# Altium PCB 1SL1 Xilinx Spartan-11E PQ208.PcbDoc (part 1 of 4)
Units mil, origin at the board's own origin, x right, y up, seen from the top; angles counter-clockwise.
Board outline 7086.61 x 1988.19 mil, 2 copper layers (Top Layer, Bottom Layer), stack 29.698 mil thick; 115 components, 126 nets, 642 pads, 225 vias.
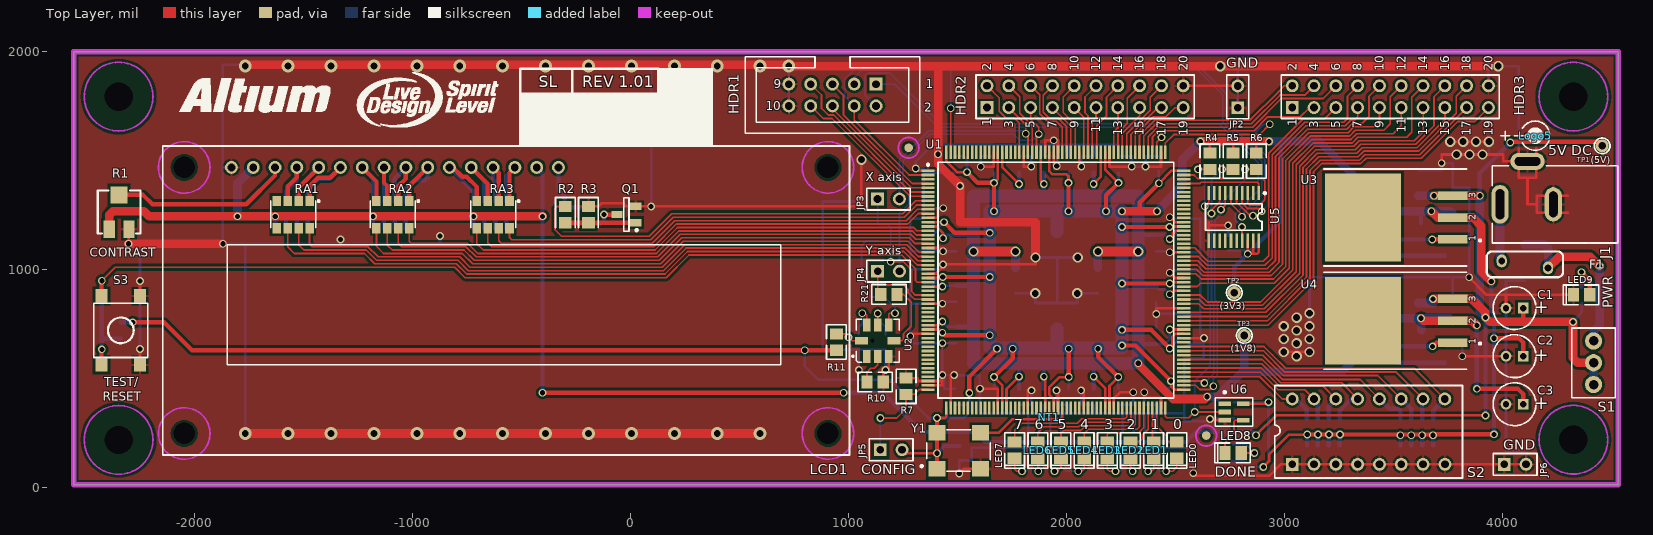
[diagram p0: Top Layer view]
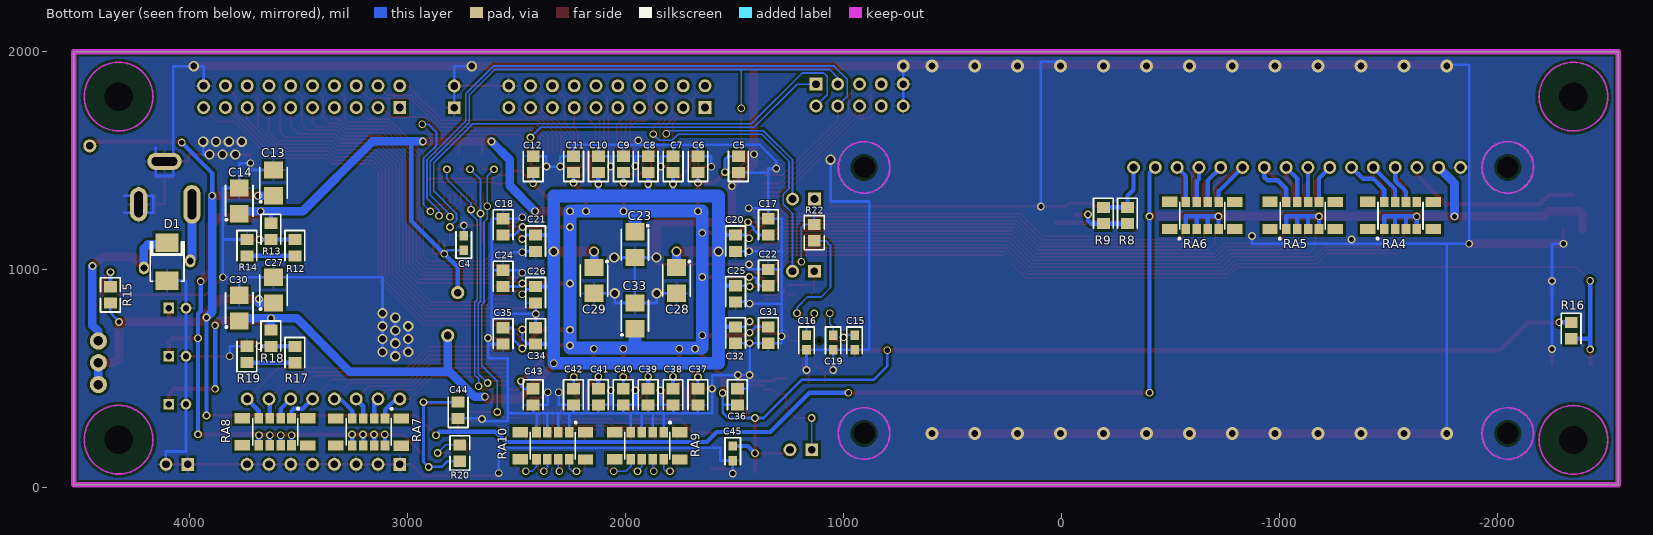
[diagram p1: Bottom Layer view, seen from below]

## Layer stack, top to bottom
Top Solder: solder mask 0.4, Solder Resist, Dk 3.5
Top Layer: signal copper 1.4
Dielectric 1: core 26.898, FR-4, Dk 4.2
Bottom Layer: signal copper 1.4
Bottom Solder: solder mask 0.4, Solder Resist, Dk 3.5

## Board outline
-2555.06,9.87 4531.55,9.87 4531.55,1998.06 -2555.06,1998.06

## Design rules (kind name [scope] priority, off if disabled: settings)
Clearance "Clearance_Power Polygon" [inpolygon and innetclass('Power')] p1: gap=11.81 ignorepadtopadclearanceinfootprint=FALSE except(0: Arc-Hole Track-Hole SMDPad-Hole THPad-Hole Via-Hole Fill-Hole Poly-Hole Region-Hole Text-Hole)
Clearance [All] p2: gap=7.87 ignorepadtopadclearanceinfootprint=FALSE except(0: Arc-Hole Track-Hole SMDPad-Hole THPad-Hole Via-Hole Fill-Hole Poly-Hole Region-Hole Text-Hole) // General
ComponentClearance ComponentClearance_D1_F1 [InComponent('D1') vs InComponent('F1')] p1 off: gap=1.18 collisioncheckmode=3 verticalgap=10 showdistances=FALSE
ComponentClearance ComponentClearance_JP4_R21 [InComponent('JP4') vs InComponent('R21')] p2 off: gap=2.76 collisioncheckmode=3 verticalgap=10 showdistances=FALSE
ComponentClearance ComponentClearance_LCD1_U2 [InComponent('LCD1') vs InComponent('U2')] p3 off: gap=3.54 collisioncheckmode=3 verticalgap=10 showdistances=FALSE
ComponentClearance ComponentClearance_U1_U6 [InComponent('U1') vs InComponent('U6')] p4 off: gap=3.94 collisioncheckmode=3 verticalgap=10 showdistances=FALSE
ComponentClearance ComponentClearance_S2 [InComponent('S2') vs InComponent('RA7') Or InComponent('RA8')] p5 off: gap=3.94 collisioncheckmode=3 verticalgap=10 showdistances=FALSE // Why is such a small clearance necessary?
ComponentClearance ComponentClearance_LCD1_R11 [InComponent('LCD1') vs InComponent('R11')] p6 off: gap=6.3 collisioncheckmode=3 verticalgap=10 showdistances=FALSE
ComponentClearance ComponentClearance_J1_Logo5 [InComponent('J1') vs InComponent('Logo5')] p7 off: gap=7.48 collisioncheckmode=3 verticalgap=10 showdistances=FALSE
ComponentClearance ComponentClearance_R2_R3 [InComponent('R2') vs InComponent('R3')] p8 off: gap=7.48 collisioncheckmode=3 verticalgap=10 showdistances=FALSE
ComponentClearance ComponentClearance_R5 [InComponent('R5') vs InComponent('R4') Or InComponent('R6')] p9 off: gap=7.48 collisioncheckmode=3 verticalgap=10 showdistances=FALSE
ComponentClearance ComponentClearance_LEDs [HasFootprint('SMD _LED') vs HasFootprint('SMD _LED')] p10 off: gap=7.48 collisioncheckmode=3 verticalgap=10 showdistances=FALSE
ComponentClearance ComponentClearance_R7_R10 [InComponent('R7') vs InComponent('R10')] p11 off: gap=9.45 collisioncheckmode=3 verticalgap=10 showdistances=FALSE
ComponentClearance ComponentClearance_U1 [InComponent('U1') vs Not InComponent('NT1') && Not InComponent('LED8')] p12 off: gap=10 collisioncheckmode=3 verticalgap=10 showdistances=FALSE
ComponentClearance ComponentClearance_General [Not InComponent('U1') vs Not InComponent('U1')] p13 off: gap=10 collisioncheckmode=3 verticalgap=10 showdistances=FALSE
ComponentClearance ComponentClearance_Default [All] p14: gap=5 collisioncheckmode=3 verticalgap=10 showdistances=FALSE
FabricationTestPointUsage TestPointUsage [All] p1 off: valid=0 allowmultiple=FALSE
FabricationTestpoint Testpoint [All] p1 off: side=3 testpointundercomponent=TRUE minsize=40 maxsize=100 preferedsize=60 minholesize=0 maxholesize=40 preferedholesize=32 testpointgrid=1 allowsidetop=TRUE allowsidebottom=TRUE usegrid=TRUE gridtolerance=0.01
HoleSize [All] p1: absolutevalues=TRUE maxlimit=130 minlimit=0 maxpercent=80.000 minpercent=20.000
PlaneConnect [All] p1: planeconnectstyle=Relief reliefexpansion=11.81 reliefentries=4 reliefconductorwidth=7.87 reliefairgap=7.87
PolygonConnect PolygonConnect_Power [innetclass('Power')] p1: thpad.connectstyle=Relief thpad.reliefconductorwidth=11.81 thpad.reliefentries=4 thpad.polygonreliefangle="90 Angle" thpad.airgapwidth=10 smdpad.connectstyle=Relief smdpad.reliefconductorwidth=11.81 smdpad.reliefentries=4 smdpad.polygonreliefangle="90 Angle" smdpad.airgapwidth=10 via.connectstyle=Direct via.reliefconductorwidth=11.81 via.reliefentries=4 via.polygonreliefangle="90 Angle" via.airgapwidth=10
PolygonConnect [All] p2: connectstyle=Relief reliefconductorwidth=7.87 reliefentries=4 polygonreliefangle="90 Angle" airgapwidth=10
RoutingVias RoutingVias_Power [innetclass('Power')] p1: holewidth=23.62 width=35.43 viastyle="Through Hole" minholewidth=23.62 minwidth=35.43 maxholewidth=31.5 maxwidth=59.06
RoutingVias [All] p2: holewidth=23.62 width=35.43 viastyle="Through Hole" minholewidth=23.62 minwidth=35.43 maxholewidth=23.62 maxwidth=35.43
SilkToSolderMaskClearance SilkscreenOverComponentPads [IsPad] p1: minsilkscreentomaskgap=10 clearancetoexposedcopper=TRUE
SolderMaskExpansion SolderMaskExpansion_Power_Vias [isvia] p1: expansion=0 istentingtop=FALSE
SolderMaskExpansion [All] p2: expansion=3.94 istentingtop=FALSE
Width Width_Power [innetclass('Power') and not inpolygon] p1: maxlimit=78.74 minlimit=11.81 preferedwidth=11.81
Width [All] p2: maxlimit=78.74 minlimit=7.87 preferedwidth=7.87
24 further rules are at their usual default settings.

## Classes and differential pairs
net class Power: 5V GND VCCINT VCCO

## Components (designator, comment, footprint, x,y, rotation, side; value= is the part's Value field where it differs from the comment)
C1 "100uF 16V" CAPPR2-5X6.8 4055.17,820.9 r180 top
C2 "100uF 16V" CAPPR2-5X6.8 4055.17,600.43 r180 top
C3 "100uF 16V" CAPPR2-5X6.8 4055.17,379.95 r180 top
C4 "10nF" CC1608-0603 2741.2,1120.11 r90 bottom
C5 "0.1uF" CC2012-0805 1482.34,1480.35 r90 bottom
C6 "0.1uF" CC2012-0805 1667.38,1480.35 r90 bottom
C7 "0.1uF" CC2012-0805 1781.55,1480.35 r90 bottom
C8 "0.1uF" CC2012-0805 1895.72,1480.35 r90 bottom
C9 "0.1uF" CC2012-0805 2009.9,1480.35 r90 bottom
C10 "0.1uF" CC2012-0805 2124.07,1480.35 r90 bottom
C11 "0.1uF" CC2012-0805 2238.24,1480.35 r90 bottom
C12 "0.1uF" CC2012-0805 2423.28,1480.35 r90 bottom
C13 "10uF" MCCT-B 3614.23,1395.7 r90 bottom
C14 "10uF" MCCT-B 3771.71,1313.02 r90 bottom
C15 "100nF" CC1608-0603 948.87,663.42 r270 bottom
C16 "100nF" CC1608-0603 1169.35,663.42 r270 bottom
C17 "0.1uF" CC2012-0805 1344.54,1193.93 r270 bottom
C18 "0.1uF" CC2012-0805 2561.08,1193.93 r270 bottom
C19 "100nF" CC1608-0603 1047.3,663.42 r270 bottom
C20 "0.1uF" CC2012-0805 1494.15,1119.13 r270 bottom
C21 "0.1uF" CC2012-0805 2411.47,1119.13 r270 bottom
C22 "0.1uF" CC2012-0805 1344.54,961.65 r270 bottom
C23 "10uF" MCCT-B 1956.75,1112.24 r270 bottom
C24 "0.1uF" CC2012-0805 2561.08,957.71 r270 bottom
C25 "0.1uF" CC2012-0805 1494.15,886.84 r270 bottom
C26 "0.1uF" CC2012-0805 2411.47,882.91 r270 bottom
C27 "10uF" MCCT-B 3614.23,903.57 r90 bottom
C28 "10uF" MCCT-B 1765.8,947.87 r270 bottom
C29 "10uF" MCCT-B 2143.76,947.87 r270 bottom
C30 "10uF" MCCT-B 3771.71,820.9 r90 bottom
C31 "0.1uF" CC2012-0805 1344.54,697.87 r270 bottom
C32 "0.1uF" CC2012-0805 1494.15,697.87 r270 bottom
C33 "10uF" MCCT-B 1956.75,785.46 r90 bottom
C34 "0.1uF" CC2012-0805 2411.47,693.93 r270 bottom
C35 "0.1uF" CC2012-0805 2561.08,693.93 r270 bottom
C36 "0.1uF" CC2012-0805 1486.28,414.4 r270 bottom
C37 "0.1uF" CC2012-0805 1667.38,414.4 r270 bottom
C38 "0.1uF" CC2012-0805 1781.55,414.4 r270 bottom
C39 "0.1uF" CC2012-0805 1895.72,414.4 r270 bottom
C40 "0.1uF" CC2012-0805 2009.9,414.4 r270 bottom
C41 "0.1uF" CC2012-0805 2124.07,414.4 r270 bottom
C42 "0.1uF" CC2012-0805 2238.24,414.4 r270 bottom
C43 "0.1uF" CC2012-0805 2423.28,414.4 r270 bottom
C44 "0.1uF" CC2012-0805 2767.77,352.39 r90 bottom
C45 "10nF" CC1608-0603 1507.93,155.54 r270 bottom
D1 "SM6T6V8A" DO214 4102.42,1033.46 r90 bottom
F1 "Polyswitch, 1.1A" RUE160_0.2 4102.42,1021.68 r0 top
HDR1 "Header 5X2" HDR2X5_LP 1126.04,1848.46 r0 top
HDR2 "Header 10X2" HDR2X10 1635.49,1740.58 r0 top locked
HDR3 "Header 10X2" HDR2X10 3035.49,1740.58 r0 top locked
J1 "KLD-0202-B" KLD-0202 4527.61,1297.28 r180 top
JP2 "GND" HDR1X2 2785.49,1740.58 r90 top locked
JP3 "X axis" HDR1X2 1133.65,1321.29 r0 top
JP4 "Y axis" HDR1X2 1133.91,990.19 r0 top
JP5 "CONFIG" HDR1X2 1145.72,171.29 r0 top
JP6 "GND" HDR1X2 4007.93,104.36 r0 top
LCD1 "162A" 162A -1830.65,1466.57 r0 top locked
LED0 "HSMH-C170" "SMD _LED" 2505.96,170.31 r90 top
LED1 "HSMH-C170" "SMD _LED" 2399.66,170.31 r90 top
LED2 "HSMH-C170" "SMD _LED" 2293.36,170.31 r90 top
LED3 "HSMH-C170" "SMD _LED" 2187.06,170.31 r90 top
LED4 "HSMH-C170" "SMD _LED" 2080.76,170.31 r90 top
LED5 "HSMH-C170" "SMD _LED" 1974.46,170.31 r90 top
LED6 "HSMH-C170" "SMD _LED" 1868.17,170.31 r90 top
LED7 "HSMH-C170" "SMD _LED" 1761.87,170.31 r90 top
LED8 "HSMH-C170" "SMD _LED" 2763.83,156.53 r0 top
LED9 "HSMH-C170" "SMD _LED" 4362.26,881.92 r0 top
Logo5 "5V" "5V SYMBOL" 4149.66,1612.24 r0 top
NT1 "GND" NT 1920.76,331.68 r270 top net-tie
Q1 "2N7002" SO-G3 -19.63,1250.03 r90 top
R1 "20K" POT4MM-2 -2346.4,1261.84 r90 top
R2 "560R" CC2012-0805 -299.16,1250.03 r270 top
R3 "10K" CC2012-0805 -192.86,1250.03 r270 top
R4 "4K7" CR2012-0805 2657.54,1495.11 r270 top
R5 "4K7" CR2012-0805 2763.83,1495.11 r270 top
R6 "4K7" CR2012-0805 2870.13,1495.11 r270 top
R7 "1K" CR2012-0805 1263.83,462.63 r270 top
R8 "68R" CC2012-0805 -303.09,1246.09 r270 bottom
R9 "68R" CC2012-0805 -192.86,1246.09 r270 bottom
R10 "680R" CR2012-0805 1122.1,482.31 r180 top
R11 "0R" CR2012-0805 944.15,665.39 r90 top
R12 "100R" CC2012-0805 3515.8,1098.45 r270 bottom
R13 "120R" CC2012-0805 3626.04,1173.25 r270 bottom
R14 "100R" CC2012-0805 3736.28,1098.45 r270 bottom
R15 "270R" CR2012-0805 4362.26,881.91 r270 bottom
R16 "4K7" CC2012-0805 -2338.53,718.53 r270 bottom
R17 "47R" CC2012-0805 3515.8,608.29 r270 bottom
R18 "120R" CC2012-0805 3626.04,683.1 r270 bottom
R19 "5R6" CC2012-0805 3736.28,608.3 r90 bottom
R20 "270R" CR2012-0805 2759.9,156.52 r270 bottom
R21 "100R" CR2012-0805 1185.09,883.89 r0 top
R22 "100R" CR2012-0805 1133.91,1167.35 r270 bottom
RA1 "270R" MNR34 -1547.19,1250.03 r270 top
RA2 "270R" MNR34 -1090.5,1250.03 r270 top
RA3 "270R" MNR34 -629.87,1250.03 r270 top
RA4 "4K7" MNR34T -1555.06,1246.09 r270 bottom
RA5 "4K7" MNR34T -1106.24,1246.09 r270 bottom
RA6 "4K7" MNR34T -645.61,1246.09 r270 bottom
RA7 "4K7" MNR34T 3177.42,252.96 r90 bottom
RA8 "4K7" MNR34T 3606.35,253.97 r90 bottom
RA9 "270R" MNR34T 1899.66,189.98 r90 bottom
RA10 "270R" MNR34T 2332.73,189.98 r90 bottom
S1 "TL36WW050" PCB_SWITCH 4417.57,470.06 r90 top
S2 "A6ER-8104" DIP-16-KEY 3035.49,104.36 r0 top
S3 "DTSM-61-NR" B3FS_SWITCH -2338.53,718.54 r270 top
TP1 "(5V)" TP 4456.75,1564.99 r0 top
TP2 "(3V3)" TP 2769.07,891.75 r0 top
TP3 "(1V8)" TP 2815.02,694.91 r0 top
U1 "XC2S300E-6PQ208C" PQ208 1950.84,949.83 r0 top locked
U2 "ADXL202E" E-8 1133.91,671.29 r90 top
U3 "LM1084IS-ADJ" TO-263 3771.71,1136.65 r90 top
U4 "LM1084IS-ADJ" TO-263 3771.71,663.42 r90 top
U5 "XCF02SVO20C" VO20 2766.79,1239.2 r180 top
U6 "SN74LVC1G04DBV" SO-G5/P.95 2767.77,344.52 r270 top
Y1 "25MHz" QSMO_4200 1405.57,68.93 r0 top

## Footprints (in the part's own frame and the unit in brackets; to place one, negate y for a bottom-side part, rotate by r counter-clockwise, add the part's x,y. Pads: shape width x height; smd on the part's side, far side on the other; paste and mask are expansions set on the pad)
"5V SYMBOL" [mil]
  silkscreen extent -158,-67 67,67
162A [mm]
  round 1.5 hole 0.9: 1(0,0) 2(2.54,0) 3(5.08,0) 4(7.62,0) 5(10.16,0) 6(12.7,0) 7(15.24,0) 8(17.78,0) 9(20.32,0) 10(22.86,0) 11(25.4,0) 12(27.94,0) 13(30.48,0) 14(33.02,0) 15(35.56,0) 16(38.1,0)
  round 2.3 hole 2.5 unplated: M1(-5.5,0) M2(69.5,0) M3(-5.5,-31) M4(69.5,-31)
  Keep-Out Layer circle w0.2: c69.5,0 r3
  Keep-Out Layer circle w0.2: c69.5,-31 r3
  Keep-Out Layer circle w0.2: c-5.5,-31 r3
  Keep-Out Layer circle w0.2: c-5.5,0 r3
  silkscreen extent -8,-33.5 72,2.5, body extent -8.01,-33.5 72,2.5, height 10.16
B3FS_SWITCH [mm]
  rect 1.6x1.4 smd: 1(3.998,-2.244) 2(-4.012,-2.244) 3(3.998,2.246) 4(-4.012,2.246)
  silkscreen extent -3.17,-3.15 3.14,3.16, body extent -4.57,-3.15 4.57,3.16, height 4.57
CAPPR2-5X6.8 [mm]
  rect 1.25x1.25 hole 0.75: 1(-0.994,-0.009)
  round 1.25 hole 0.75: 2(1.006,-0.009)
  silkscreen extent -2.49,-2.51 2.5,2.49, body extent -2.49,-2.51 2.51,2.49, height 10.16
CC1608-0603 [mm]
  rect 1.1x1 smd: 1(-0.843,0.001) 2(0.857,0.001)
  silkscreen extent -1.79,-0.9 1.31,0.9, body extent -1.46,-0.57 1.46,0.57, height 0.76
CC2012-0805 [mm]
  rect 1.3x1.5 smd: 1(-0.945,-0.007) 2(0.955,-0.007)
  silkscreen extent -1.99,-1.16 1.51,1.14, body extent -1.52,-0.7 1.52,0.7, height 0.76
CR2012-0805 [mm]
  rect 1.3x1.5 smd: 1(-0.946,0) 2(0.954,0)
  silkscreen extent -2,-1.15 2,1.15, body extent -1.52,-0.7 1.52,0.7, height 0.76
DIP-16-KEY [mm]
  rect 1.5x1.5 hole 0.9: 1(-0.011,0.001)
  round 1.5 hole 0.9: 2(2.529,0.001) 3(5.069,0.001) 4(7.609,0.001) 5(10.149,0.001) 6(12.689,0.001) 7(15.229,0.001) 8(17.789,0.001) 9(17.769,7.621) 10(15.229,7.621) 11(12.689,7.621) 12(10.149,7.621) 13(7.609,7.621) 14(5.069,7.621) 15(2.529,7.621) 16(-0.011,7.621)
  silkscreen extent -2.06,-1.59 19.82,9.2, body extent -2.03,-1.52 19.81,9.14, height 7.11
DO214 [mil]
  rect 85x106.3 smd: 1(-87.01,0.18) 2(87.99,0.18)
  silkscreen extent -90,-77 90,78, body extent -125,-50 125,50, height 50
E-8 [mil]
  round 15 hole 20 unplated: 0(-0.02,23.98)
  rect 60x35 smd: 1(-72.85,49.98) 2(-72.85,-0.02) 3(-72.85,-50.02) 5(72.82,-50.02) 6(72.82,-0.02) 7(72.82,49.98)
  rect 35x60 smd: 4(-0.02,-74.82) 8(-0.02,74.79)
  silkscreen extent -98,-98 99,118, body extent -95,-95 95,95, height 80
HDR1X2 [mm]
  rect 1.5x1.5 hole 0.9: 1(-0.011,0.007)
  round 1.5 hole 0.9: 2(2.529,0.007)
  silkscreen extent -1.28,-1.26 3.8,1.28, body extent -1.27,-1.27 3.81,1.27, height 10
HDR2X5_LP [mm]
  rect 1.5x1.5 hole 0.9: 1(0.003,0.004)
  round 1.5 hole 0.9: 2(0.003,-2.536) 3(-2.537,0.004) 4(-2.537,-2.536) 5(-5.077,0.004) 6(-5.077,-2.536) 7(-7.617,0.004) 8(-7.617,-2.536) 9(-10.157,0.004) 10(-10.157,-2.536)
  silkscreen extent -15.24,-5.71 5.08,3.18, body extent -15.24,-5.71 5.08,3.18, height 10
HDR2X10 [mm]
  rect 1.5x1.5 hole 0.9: 1(-0.011,0.007)
  round 1.5 hole 0.9: 2(-0.011,2.547) 3(2.529,0.007) 4(2.529,2.547) 5(5.069,0.007) 6(5.069,2.547) 7(7.609,0.007) 8(7.609,2.547) 9(10.149,0.007) 10(10.149,2.547) 11(12.689,0.007) 12(12.689,2.547) 13(15.229,0.007) 14(15.229,2.547) 15(17.769,0.007) 16(17.769,2.547) 17(20.309,0.007) 18(20.309,2.547) 19(22.849,0.007) 20(22.849,2.547)
  silkscreen extent -1.28,-1.26 24.12,3.82, body extent -1.27,-1.27 24.13,3.81, height 10
KLD-0202 [mm]
  oval 2x4.5 hole 1 slot 3.5 at 90 deg: 1(13.692,-0.001)
  oval 2x4 hole 1 slot 3 at 90 deg: 2(7.492,-0.001)
  oval 4x2 hole 1 slot 3 at 0 deg: 3(10.492,-5.001)
  silkscreen extent -0.01,-4.5 14.59,4.5, body extent 0,-4.44 14.6,4.45, height 7.62
MCCT-B [mm]
  rect 2x2.2 smd: 1(-1.505,-0.002) 2(1.495,-0.002)
  silkscreen extent -2.3,-1.6 1.8,1.6, body extent -2.29,-0.89 2.29,0.89, height 1.27
MNR34 [mm]
  rect 1.2x1 smd: 1(-1.578,1.898) 2(-1.578,0.628) 3(-1.578,-0.642) 4(-1.578,-1.912) 5(1.572,-1.912) 6(1.572,-0.642) 7(1.572,0.628) 8(1.572,1.898)
  silkscreen extent -1.68,-2.62 1.55,3.06, body extent -2.03,-2.29 2.03,2.29, height 1.27
MNR34T [mm]
  rect 1.2x1 smd: 1(1.575,-1.896) 2(1.575,-0.626) 3(1.575,0.644) 4(1.575,1.914) 5(-1.575,1.914) 6(-1.575,0.644) 7(-1.575,-0.626) 8(-1.575,-1.896)
  rect 1.2x1.8 smd: STP(-1.6,-3.801) STP(-1.575,3.819) STP(1.575,-3.801) STP(1.575,3.819)
  silkscreen extent -1.55,-2.76 2.79,2.62, body extent -1.65,-2.71 1.68,2.72, height 2
NT [mm]
  rect 0.2x0.2 smd: 1(0.01,0.011) 2(0.51,0.011)
  Top Layer lines w0.3: 0.51,0.011 0.01,0.011
PCB_SWITCH [mm]
  round 2 hole 1.1: 1(0.011,0.005) 2(2.551,0.005) 3(5.091,0.005)
  silkscreen extent -1.54,-2.53 6.59,2.55, body extent -1.52,-2.54 6.6,2.54, height 15
POT4MM-2 [mm]
  rect 2x1.3 smd: CCW(-2.008,-1.162) CW(-2.008,1.138)
  rect 2x2 smd: W(1.992,-0.012)
  silkscreen extent -2.51,-2.51 2.49,2.49, body extent -2.92,-2.41 2.92,2.41, height 3.05
PQ208 [mm]
  rect 1.55x0.3 smd: 1(-14.902,12.738) 2(-14.902,12.238) 3(-14.902,11.738) 4(-14.902,11.238) 5(-14.902,10.738) 6(-14.902,10.238) 7(-14.902,9.738) 8(-14.902,9.238) 9(-14.902,8.738) 10(-14.902,8.238) 11(-14.902,7.738) 12(-14.902,7.238) 13(-14.902,6.738) 14(-14.902,6.238) 15(-14.902,5.738) 16(-14.902,5.238) 17(-14.902,4.738) 18(-14.902,4.238) 19(-14.902,3.738) 20(-14.902,3.238) 21(-14.902,2.738) 22(-14.902,2.238) 23(-14.902,1.738) 24(-14.902,1.238) 25(-14.902,0.738) 26(-14.902,0.238) 27(-14.902,-0.262) 28(-14.902,-0.762) 29(-14.902,-1.262) 30(-14.902,-1.762) 31(-14.902,-2.262) 32(-14.902,-2.762) 33(-14.902,-3.262) 34(-14.902,-3.762) 35(-14.902,-4.262) 36(-14.902,-4.762) 37(-14.902,-5.262) 38(-14.902,-5.762) 39(-14.902,-6.262) 40(-14.902,-6.762) 41(-14.902,-7.262) 42(-14.902,-7.762) 43(-14.902,-8.262) 44(-14.902,-8.762) 45(-14.902,-9.262) 46(-14.902,-9.762) 47(-14.902,-10.262) 48(-14.902,-10.762) 49(-14.902,-11.262) 50(-14.902,-11.762) 51(-14.902,-12.262) 52(-14.902,-12.762) 105(14.898,-12.762) 106(14.898,-12.262) 107(14.898,-11.762) 108(14.898,-11.262) 109(14.898,-10.762) 110(14.898,-10.262) 111(14.898,-9.762) 112(14.898,-9.262) 113(14.898,-8.762) 114(14.898,-8.262) 115(14.898,-7.762) 116(14.898,-7.262) 117(14.898,-6.762) 118(14.898,-6.262) 119(14.898,-5.762) 120(14.898,-5.262) 121(14.898,-4.762) 122(14.898,-4.262) 123(14.898,-3.762) 124(14.898,-3.262) 125(14.898,-2.762) 126(14.898,-2.262) 127(14.898,-1.762) 128(14.898,-1.262) 129(14.898,-0.762) 130(14.898,-0.262) 131(14.898,0.238) 132(14.898,0.738) 133(14.898,1.238) 134(14.898,1.738) 135(14.898,2.238) 136(14.898,2.738) 137(14.898,3.238) 138(14.898,3.738) 139(14.898,4.238) 140(14.898,4.738) 141(14.898,5.238) 142(14.898,5.738) 143(14.898,6.238) 144(14.898,6.738) 145(14.898,7.238) 146(14.898,7.738) 147(14.898,8.238) 148(14.898,8.738) 149(14.898,9.238) 150(14.898,9.738) 151(14.898,10.238) 152(14.898,10.738) 153(14.898,11.238) 154(14.898,11.738) 155(14.898,12.238) 156(14.898,12.738)
  rect 0.3x1.55 smd: 53(-12.752,-14.912) 54(-12.252,-14.912) 55(-11.752,-14.912) 56(-11.252,-14.912) 57(-10.752,-14.912) 58(-10.252,-14.912) 59(-9.752,-14.912) 60(-9.252,-14.912) 61(-8.752,-14.912) 62(-8.252,-14.912) 63(-7.752,-14.912) 64(-7.252,-14.912) 65(-6.752,-14.912) 66(-6.252,-14.912) 67(-5.752,-14.912) 68(-5.252,-14.912) 69(-4.752,-14.912) 70(-4.252,-14.912) 71(-3.752,-14.912) 72(-3.252,-14.912) 73(-2.752,-14.912) 74(-2.252,-14.912) 75(-1.752,-14.912) 76(-1.252,-14.912) 77(-0.752,-14.912) 78(-0.252,-14.912) 79(0.248,-14.912) 80(0.748,-14.912) 81(1.248,-14.912) 82(1.748,-14.912) 83(2.248,-14.912) 84(2.748,-14.912) 85(3.248,-14.912) 86(3.748,-14.912) 87(4.248,-14.912) 88(4.748,-14.912) 89(5.248,-14.912) 90(5.748,-14.912) 91(6.248,-14.912) 92(6.748,-14.912) 93(7.248,-14.912) 94(7.748,-14.912) 95(8.248,-14.912) 96(8.748,-14.912) 97(9.248,-14.912) 98(9.748,-14.912) 99(10.248,-14.912) 100(10.748,-14.912) 101(11.248,-14.912) 102(11.748,-14.912) 103(12.248,-14.912) 104(12.748,-14.912) 157(12.748,14.888) 158(12.248,14.888) 159(11.748,14.888) 160(11.248,14.888) 161(10.748,14.888) 162(10.248,14.888) 163(9.748,14.888) 164(9.248,14.888) 165(8.748,14.888) 166(8.248,14.888) 167(7.748,14.888) 168(7.248,14.888) 169(6.748,14.888) 170(6.248,14.888) 171(5.748,14.888) 172(5.248,14.888) 173(4.748,14.888) 174(4.248,14.888) 175(3.748,14.888) 176(3.248,14.888) 177(2.748,14.888) 178(2.248,14.888) 179(1.748,14.888) 180(1.248,14.888) 181(0.748,14.888) 182(0.248,14.888) 183(-0.252,14.888) 184(-0.752,14.888) 185(-1.252,14.888) 186(-1.752,14.888) 187(-2.252,14.888) 188(-2.752,14.888) 189(-3.252,14.888) 190(-3.752,14.888) 191(-4.252,14.888) 192(-4.752,14.888) 193(-5.252,14.888) 194(-5.752,14.888) 195(-6.252,14.888) 196(-6.752,14.888) 197(-7.252,14.888) 198(-7.752,14.888) 199(-8.252,14.888) 200(-8.752,14.888) 201(-9.252,14.888) 202(-9.752,14.888) 203(-10.252,14.888) 204(-10.752,14.888) 205(-11.252,14.888) 206(-11.752,14.888) 207(-12.252,14.888) 208(-12.752,14.888)
  round 1 smd: FID1(-17.152,15.413) FID2(17.523,-18.112)
  Top Layer keep-out circle w0.2: c17.523,-18.137 r1.2
  Top Layer keep-out circle w0.2: c-17.152,15.413 r1.2
  silkscreen extent -15.03,-13.74 13.72,13.71, body extent -15.35,-15.36 15.35,15.34, height 2.5
QSMO_4200 [mm]
  rect 2x1.8 smd: 1(-0.009,0.39) 2(5.071,0.39) 3(5.071,4.59) 4(-0.009,4.59)
  silkscreen extent -1.91,0.09 6.21,4.94, body extent -1.14,-0.32 6.1,5.3, height 1.5
RUE160_0.2 [mm]
  oval 1.2x1.5 hole 0.8: 1(-2.7,0.4) 2(2.7,-0.4)
  silkscreen extent -4.45,-1.5 4.45,1.5, body extent -4.45,-1.5 4.45,1.5, height 12
"SMD _LED" [mm]
  rect 1.3x1.6 smd: 1(0.948,0.006) 2(-0.952,0.006)
  silkscreen extent -2.13,-1.14 2,1.16, body extent -1.52,-0.64 1.52,0.64, height 1.27
SO-G3 [mm]
  rect 0.85x1.3 smd: 1(-0.939,-1.107) 2(0.961,-1.107) 3(0.011,1.093)
  silkscreen extent -1.94,-1.33 1.96,0.29, body extent -1.65,-1.52 1.65,1.51, height 2.54
SO-G5/P.95 [mm]
  rect 0.55x1.45 smd: 1(-0.954,-1.07) 2(-0.004,-1.07) 3(0.946,-1.07) 4(0.946,1.08) 5(-0.954,1.08)
  silkscreen extent -2.43,-2.19 1.65,2.21, body extent -1.27,-1.78 1.27,1.78, height 0.89
TO-263 [mm]
  rect 1x3.4 smd: 1(-0.006,0.009) 2(2.534,0.009) 3(5.074,0.009)
  rect 10.25x8.9 smd: 4(2.534,10.459)
  silkscreen extent -3.11,-3.29 8.19,15.01, body extent -2.29,-1.14 7.37,14.35, height 2.03
TP [mil]
  round 60 hole 35.43: 1(0.14,0.45)
  silkscreen extent -36,-36 36,36, body extent -36,-36 36,36
VO20 [mm]
  rect 0.3x1.65 smd: 1(-2.929,-2.778) 2(-2.279,-2.778) 3(-1.629,-2.778) 4(-0.979,-2.778) 5(-0.329,-2.778) 6(0.321,-2.778) 7(0.971,-2.778) 8(1.621,-2.778) 9(2.271,-2.778) 10(2.921,-2.778) 11(2.921,2.772) 12(2.271,2.772) 13(1.621,2.772) 14(0.971,2.772) 15(0.321,2.772) 16(-0.329,2.772) 17(-0.979,2.772) 18(-1.629,2.772) 19(-2.279,2.772) 20(-2.929,2.772)
  silkscreen extent -3.75,-2.9 3.3,1.55, body extent -3.3,-3.56 3.3,3.55, height 1.52

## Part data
C1 C2 C3: library part CAP_POLAR_1, "Polar Capacitor"
C4 C5 C6 C7 C8 C9 C10 C11 C12 C15 C16 C17 C18 C19 C20 C21 C22 C24 C25 C26 C31 C32 C34 C35 C36 C37 C38 C39 C40 C41 C42 C43 C44 C45: library part CAP, "Capacitor"
C13 C14 C23 C27 C28 C29 C30 C33: library part CAP_POLAR, "Polar Capacitor", Capacitor Type=Tant
D1: library part BZG03C13, "Zener Diode, 6.2V, 5W", Manufacturer=Microsemi
F1: library part "Fuse 2", "Polyswitch 1.1A, Raychem RUE110"
HDR1: "Header, 5-Pin, Dual row"
HDR2 HDR3: "Header, 10-Pin, Dual row"
J1: "Low Voltage Power Supply Connector", Manufacturer=Kycon
JP2 JP3 JP4 JP5 JP6: library part "Jumper, 2-Pin", "Jumper, 2-Pin"
LCD1: "16 char * 2 line LCD character display with b/light"
LED0 LED1 LED2 LED3 LED4 LED5 LED6 LED7 LED8 LED9: library part HSMX-C670, "Typical RED GaAs SMD LED Agilent make"
NT1: library part "Jumper, 2-Pin_1", "Jumper, 2-Pin"
Q1: "N Channel Mosfet"
R1: library part "RPot SM", "Square Trimming Potentiometer"
R2 R3 R4 R5 R6 R7 R8 R9 R11 R12 R13 R14 R15 R16 R17 R18 R19 R20: library part RES, "Resistor"
R10 R21 R22: library part Res1, "Resistor"
RA1 RA2 RA3 RA4 RA5 RA6 RA7 RA8 RA9 RA10: library part MNR34, "3216x4 Resistor Array"
S1: library part PCB_MOUNT_SWITCH, "SPDT Subminiature Toggle Switch"
S2: "DIP Switch Side actuator long liver Piano Key"
S3: library part B3FS, "SPNA SMD Keyboard Switch"
TP1 TP2 TP3: library part TestPin
U1: "Spartan-IIE 1.8V FPGA, 208-Pin PQFP, Standard Performance, Commercial Grade", PackageDocument="ver1.1, Oct-2002"
U2: "Accelerometer with Digital Output"
U3 U4: "5A Low Dropout Possitive Regulators"
U5: "XCF00S Series, Platform Flash In-System Programmable Configuration 3.3V PROM, 20-Pin TSOP, 2-Megabit, Commercial Grade", PackageDocument="ver1.0, May-2003"
U6: library part SN74AHC1G04DBVR, Manufacturer=TI
Y1: library part QSMO_4200, "Surface Mount Crystal Oscillator"

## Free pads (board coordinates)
  round 35.43 hole 23.62 mask+3.94: 0(1430.17,660.46)
  round 118.11 hole 129.92 unplated: M3(-2348.37,216.57) M3(-2348.37,1791.37) M3(4324.86,1791.37) M3(4324.86,217.55)

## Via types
v1: diameter 35.43, hole 23.62, Top Layer to Bottom Layer, tented both sides, 168 vias
v2: diameter 59.06, hole 31.5, Top Layer to Bottom Layer, tented both sides, 27 vias
v3: diameter 47.24, hole 31.5, Top Layer to Bottom Layer, 18 vias
v4: diameter 47.24, hole 31.5, Top Layer to Bottom Layer, tented both sides, 11 vias
v5: diameter 35.43, hole 23.62, Top Layer to Bottom Layer, 1 vias

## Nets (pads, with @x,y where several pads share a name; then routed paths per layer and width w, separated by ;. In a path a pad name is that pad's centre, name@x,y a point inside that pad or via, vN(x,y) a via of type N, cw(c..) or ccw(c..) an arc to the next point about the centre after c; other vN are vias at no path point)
5V: C1.1 C13.1 C27.1 LCD1.2 LCD1.15 R1.CW R15.2 RA4.1 RA4.2 RA4.3 RA4.4 RA5.1 RA5.2 RA5.3 RA5.4 RA6.1 RA6.2 RA6.3 RA6.4 S1.1 S1.2 TP1.1 U3.3 U4.3 | length 12355.5
  Top Layer w11.81: v1(2869.15,238.22) 2959.7,328.77 v1(3921.32,328.77)
  Top Layer w19.68: v1(-403.49,433.1) v1(977.42,433.1) ; v1(4035.49,1580.74) 4039.43,1584.68 4444.94,1584.68 TP1.1@4464.62,1564.99 ; 4094.54,757.91 C1.1@4094.54,820.9
  Top Layer w39.37: R1.CW@-2391.68,1183.1 -2391.68,1248.06 -2373.96,1265.78 -2232.23,1265.78 -2208.61,1242.16 v1(-403.49,1242.16) ; v1(3681.16,863.22) 3858.32,864.2 3921.32,801.21 v1(3921.32,778.57) 3941.98,757.91 v1(4322.89,757.91) 4322.89,592.55 4344.94,570.5 S1.2@4417.38,570.5 ; v1(3685.09,1336.65) v1(3895.72,1336.65)
  Bottom Layer w11.81: v1(4322.89,757.91) 4362.26,801.21 R15.2@4362.26,844.52
  Bottom Layer w19.68: RA4.4@-1630.06,1184.09 v1(-1629.87,1242.16) -1479.87,1242.16 ; RA4.3@-1580.06,1184.09 -1580.06,1241.96 ; RA4.2@-1530.06,1184.09 -1530.06,1241.96 ; RA4.1@-1480.06,1184.09 -1480.06,1241.96 ; RA5.4@-1181.24,1184.09 v1(-1181.05,1242.16) -1031.05,1242.16 ; RA5.3@-1131.24,1184.09 -1131.24,1241.96 ; RA5.2@-1081.24,1184.09 -1081.24,1241.96 ; RA5.1@-1031.24,1184.09 -1031.24,1241.96 ; RA6.4@-720.61,1184.09 v1(-720.42,1242.16) -570.42,1242.16 ; RA6.3@-670.61,1184.09 -670.61,1241.96 ; RA6.2@-620.61,1184.09 -620.61,1241.96 ; RA6.1@-570.61,1184.09 -570.61,1241.96 ; LCD1.15@-430.65,1466.57 -403.49,1439.4 v1(-403.49,433.1) ; v1(977.42,433.1) 1155.57,433.1 1334.7,253.97 1580.76,252.98 1627.02,206.72 2547.3,206.72 2594.54,253.97 2853.4,253.97 v1(2869.15,238.22) ; v1(3895.72,1336.65) 3895.72,1440.98 v1(4035.49,1580.74) ; v1(3921.32,328.77) v1(3921.32,778.57)
  Bottom Layer w39.37: v1(-1803.09,1242.16) -1803.09,1394.13 LCD1.2@-1730.65,1466.57 ; C27.1@3614.23,844.52 3681.16,844.52 v1(3681.16,863.22) ; C13.1@3614.23,1336.65 v1(3685.09,1336.65) ; v1(3895.72,1336.65) 3895.72,804.17 v1(3921.32,778.57) ; S1.1@4417.38,470.5 S1.2@4417.38,570.5
CCLK: U1.155 U5.3 | length 609.9
  Top Layer w7.87: U1.155@2537.46,1432.12 2583.72,1432.12 2600.45,1415.39 2899.66,1415.39 2909.5,1405.54 2909.5,1316.96 2886.87,1294.32 2837.65,1294.32 2830.76,1301.21 U5.3@2830.76,1348.46
CLK_BRD: NT1.2 U1.80 Y1.3 | length 446
  Top Layer w11.81: Y1.3@1605.57,250.03 1689.03,250.03 1750.06,311.06 1970.53,311.06 1980.28,320.81 U1.80@1980.28,362.75
CLK_BRD_1: NT1.1 U1.77
DIN: U1.153 U5.1 | length 393.1
  Top Layer w7.87: U1.153@2537.46,1392.75 2612.26,1392.75 2618.17,1398.65 2875.06,1398.65 2881.94,1391.76 U5.1@2881.94,1348.46
DONE: R4.2 U1.104 U5.10 U6.2 | length 1614
  Top Layer w7.87: U1.104@2452.81,363.22 2452.81,324.83 2459.7,317.94 2561.08,317.94 v1(2587.65,344.52) U6.2@2725.45,344.52 ; v1(2602.42,1457.71) R4.2@2657.54,1457.71 ; v1(2633.91,1288.42) 2651.63,1306.13 U5.10@2651.63,1348.46
  Bottom Layer w7.87: v1(2587.65,344.52) 2587.65,485.27 2659.5,557.12 2659.5,835.31 2648.68,846.13 2648.68,1216.13 2633.91,1230.9 2633.91,1426.21 v1(2602.42,1457.71)
GND: C1.2 C2.2 C3.2 C4.2 C5.1 C6.2 C7.2 C8.2 C9.2 C10.2 C11.2 C12.2 C13.2 C14.2 C15.2 C16.2 C17.1 C18.1 C19.2 C20.2 C21.2 C22.1 C23.2 C24.1 C25.2 C26.2 C27.2 C28.2 C29.2 C30.2 C31.2 C32.2 C33.2 C34.1 C35.2 C36.1 C37.2 C38.2 C39.2 C40.2 C41.2 C42.2 C43.2 C44.1 C45.2 D1.1 HDR1.9 HDR1.10 HDR2.20 HDR3.20 J1.2 J1.3 JP2.1 JP2.2 JP6.1 JP6.2 LCD1.1 LED9.2 pad.0 Q1.2 R1.CCW R3.1 R7.1 R10.1 R14.1 R19.2 RA9.1 RA9.2 RA9.3 RA9.4 RA10.1 RA10.2 RA10.3 RA10.4 S2.1 S2.2 S2.3 S2.4 S2.5 S2.6 S2.7 S2.8 S3.3 S3.4 U1.1 U1.12 U1.19 U1.25 U1.32 U1.39 U1.50 U1.51 U1.54 U1.65 U1.72 U1.79 U1.85 U1.92 U1.103 U1.117 U1.124 U1.131 U1.137 U1.144 U1.158 U1.170 U1.177 U1.182 U1.183 U1.185 U1.190 U1.197 U2.3 U5.11 U6.3 Y1.2 | length 42228.3
  Top Layer w11.81: v1(-2303.09,1116.17) -2301.13,1118.14 R1.CCW@-2301.13,1183.1 ; S3.3@-2250.34,560.66 v1(-2250.34,633.5) ; S3.4@-2250.34,876.02 v1(-2250.34,945.31) ; R3.1@-192.86,1287.43 -147.58,1287.43 -133.8,1301.21 -32.42,1301.21 -18.64,1287.43 23.68,1287.43 v1(94.54,1287.43) 1059.11,1287.43 v4(1059.11,1502) ; R10.1@1159.5,482.31 1159.5,537.43 v1(1169.35,537.43) 1183.91,537.43 U2.3@1183.91,598.46 ; R7.1@1263.39,500.24 1317.97,500.24 1317.97,486.76 U1.50@1364.14,486.76 1430.17,486.76 ; v1(1283.52,691.96) 1283.52,703.3 U1.39@1364.14,703.3 ; v1(1308.13,1461.65) 1308.13,1451.8 U1.1@1364.23,1451.8 ; U1.32@1364.14,841.09 v1@1430.17,841.09 ; U1.25@1364.14,978.89 1401.1,978.89 1433.13,1010.91 v1(1433.13,1021.68) 1857.34,1021.68 v4(1857.34,1053.18) ; U1.19@1364.14,1097 1433.13,1097 v1(1433.13,1081.72) ; U1.12@1364.14,1234.8 1409.5,1234.8 1409.5,1279.56 v1(1434.11,1279.56) ; U1.51@1364.23,467.55 1430.17,467.55 1430.17,486.76 ; v1(1430.17,514.8) 1430.17,486.76 ; U1.54@1468.47,365.06 1468.47,513.81 v1(1484.31,513.81) ; v1(1507.93,62.04) 1530.57,84.68 Y1.2@1605.57,84.68 ; v1(1602.42,451.8) 1685.01,451.8 U1.65@1685.01,362.75 ; v1(1606.35,1469.52) 1665.32,1469.52 U1.197@1665.32,1535.98 ; U1.190@1803.12,1535.98 1803.12,1470.5 v1(1837.65,1470.5) ; U1.72@1822.8,362.75 1822.8,443.93 v1(1838.64,443.93) ; U1.185@1901.54,1535.98 1901.54,1590.58 ; 1901.63,1590.58 v1(1941,1590.58) 1960.6,1590.58 ; U1.183@1940.91,1535.98 1940.91,1473.39 v1(1954.78,1473.39) ; v1(1953.8,443.93) v1@1960.69,443.93 ; U1.79@1960.6,362.75 1960.6,398 v1@1960.69,443.92 ; U1.182@1960.6,1535.98 1960.6,1590.58 ; 1960.69,1590.58 1960.6,1590.58 ; v1@2059.02,1470.5 U1.177@2059.02,1535.98 ; v1(2066.98,443.93) v1@2078.71,443.93 ; U1.85@2078.71,362.75 v1@2078.71,443.93 ; v1@2078.8,443.93 v1@2078.71,443.93 ; U1.170@2196.82,1535.98 2196.82,1470.5 v1(2299.27,1470.5) ; U1.92@2216.5,362.75 2216.5,405.5 2246.07,435.07 v1(2306.16,435.07) ; v1(2356.35,435.07) 2356.35,409.48 2433.04,409.48 U1.103@2433.04,362.75 ; v1(2362.26,1470.5) 2433.04,1470.5 ; v1(2411.47,794.32) 2411.47,821.41 U1.124@2537.37,821.41 ; U1.158@2433.04,1535.98 2433.04,1470.5 ; 2433.13,1470.5 2433.04,1470.5 ; v1(2473.48,983.3) 2497.57,959.2 U1.131@2537.37,959.2 ; v5(2473.48,1077.32) U1.137@2537.37,1077.32 ; v1(2473.48,1238.22) 2496.59,1215.11 U1.144@2537.37,1215.11 ; HDR2.20@2535.49,1840.58 JP2.2@2785.49,1840.58 ; U1.117@2537.37,683.61 v1@2629.98,683.61 ; v1(2580.76,64.01) 2590.61,52.2 2930.17,52.2 2982.34,104.36 S2.6@3535.05,104.42 JP6.2@4107.93,104.36 ; U5.11@2651.63,1129.95 2651.63,1200.82 ; 2651.63,1215.58 2651.63,1200.82 ; v1(2657.52,312.04) 2657.54,307.12 U6.3@2725.45,307.12 ; v1(2741.2,1200.82) 2651.63,1200.82 ; v3(2996.12,620.11) v3@3055.17,620.11 ; v3(3055.17,600.43) v3@3055.17,620.11 ; v3(3114.23,620.11) v3@3055.17,620.11 ; v1(3720.53,1486.25) 3720.53,1525.62 v3(3789.43,1525.62) v3(3848.48,1525.62) v3(3907.54,1525.62) 4003.01,1525.62 4003.01,1494.13 4074.86,1494.13 J1.3@4074.86,1486.25 ; v3(3759.9,1584.68) v3(3818.95,1584.68) v3(3878.01,1584.68) v3(3937.06,1584.68) ; v1(3815.02,600.43) C2.2@4015.8,600.43 ; v1(3846.51,962.63) 3927.22,881.92 4015.8,881.92 ; C1.2@4015.8,836.65 4015.8,881.92 ; 4074.86,1555.34 4074.86,1419.32 4114.23,1419.32 ; 4153.6,1555.34 4153.6,1419.32 4114.23,1419.32 ; 4234.31,881.92 4324.86,881.92 4015.8,881.92 ; 4299.27,1257.91 4157.54,1257.91 4157.54,1298.26 ; 4299.27,1336.65 4232.65,1336.65 4157.54,1336.65 4157.54,1298.26 ; 4114.23,1419.32 4114.23,1298.26 4157.54,1298.26
  Top Layer w39.37: v1(-2303.09,1116.17) v1(-1870.02,1116.17) ; v2(-1767.66,246.09) v2(-1570.81,246.09) v2(-1373.96,246.09) v2(-1177.11,246.09) v2(-980.26,246.09) v2(-783.41,246.09) v2(-586.56,246.09) v2(-389.71,246.09) v2(-192.86,246.09) v2(3.99,246.09) v2(200.84,246.09) v2(397.69,246.09) v2(594.54,246.09) ; v2@-1767.66,1937.04 -980.26,1937.04 -389.71,1937.04 v2@725.45,1937.04 ; v2(725.45,1931.13) 1410.49,1931.13 ; 1410.49,1931.33 1410.49,1931.13 ; v4(1857.34,1053.18) 1857.34,1214.6 1511.87,1214.6 v1(1511.87,1380.94) 1410.49,1482.31 v1(1410.49,1526.61) 1410.49,1931.13 ; v4(3980.37,1931.13) v4(2704.76,1931.13) 1410.49,1931.13
  Bottom Layer w11.81: v1(-2303.09,1116.17) -2250.34,1116.17 v1(-2250.34,945.31) v1(-2250.34,633.5) ; LCD1.1@-1830.65,1466.57 -1870.02,1466.57 ; v2(-1767.66,246.09) -1767.66,1116.17 ; v2@-1767.66,1937.04 -1870.02,1937.04 -1870.02,1466.57 ; v1(-1330.65,1135.86) -1330.65,1116.17 ; v1(-873.97,1151.61) -873.97,1116.17 -1330.65,1116.17 ; v2@3.99,1950.81 94.54,1950.81 v1(94.54,1287.43) ; HDR1.9@725.45,1849.05 v2(725.45,1931.13) v2@725.45,1937.04 ; HDR1.10@726.04,1748.46 HDR1.9@726.04,1848.46 ; v1(1047.3,537.42) C19.2@1047.3,629.95 ; v4(1059.11,1502) 1059.11,1310.07 881.94,1310.07 881.94,629.95 C19.2@1047.3,629.95 ; v1@1170.43,548.36 v1(1169.35,537.43) 1169.35,629.95 C19.2@1047.3,629.95 ; v1(1433.13,1021.68) 1433.13,999.05 1344.54,999.05 1283.52,999.05 ; v1(1434.11,1279.56) 1344.54,1279.56 ; 1439.82,451.81 1439.82,505.15 v1(1430.17,514.8) ; 1439.83,451.8 C36.1@1486.28,451.8 ; C5.1@1482.34,1442.94 1344.54,1442.94 ; C32.2@1494.15,660.46 pad.0@1430.17,660.46 ; C25.2@1494.15,849.44 1438.05,849.44 v1(1430.17,841.57) 1283.52,841.57 ; C20.2@1494.15,1081.72 v1(1433.13,1081.72) 1283.52,1081.72 ; v1(1507.93,62.04) 1507.93,122.08 1565.02,122.08 1565.02,180.15 2580.76,180.15 v1(2580.76,64.01) ; v1(1606.35,1469.52) 1606.35,1517.75 1667.38,1517.75 1667.38,1569.91 ; C37.2@1667.38,377 1667.38,376.79 1667.38,339.6 ; C28.2@1765.8,888.81 v4(1856.35,888.81) 1856.35,844.52 C33.2@1956.75,844.52 ; RA9.1@1824.66,251.99 1824.66,339.4 ; v1(1837.65,1470.5) 1837.65,1517.75 1781.55,1517.75 1781.55,1517.96 1781.55,1569.91 ; v1(1838.64,443.93) 1838.64,377 1781.55,377 1781.55,340.58 1780.57,339.6 ; v4(1857.34,1053.18) C23.2@1956.75,1053.18 ; RA9.2@1874.66,251.99 1874.66,339.4 ; 1895.72,339.6 C39.2@1895.72,377 ; RA9.3@1924.66,251.99 1924.66,339.4 ; v1(1941,1590.58) 1941,1569.91 ; v1(1953.8,443.93) 1953.8,377 2009.9,377 2009.9,339.6 ; v1(1954.78,1473.39) 1954.78,1517.75 1895.72,1517.75 1895.72,1569.91 ; RA9.4@1974.66,251.99 1974.66,339.4 ; C9.2@2009.9,1517.75 2009.9,1569.91 ; v4(2051.24,1053.18) 1956.82,1053.18 C23.2@1956.75,1053.18 ; v1(2066.98,443.93) 2066.98,377 2124.07,377 2124.07,339.6 ; v1(2067.97,1470.5) 2067.97,1517.75 2124.07,1517.75 2124.07,1517.96 2124.07,1569.91 ; C29.2@2143.76,888.81 v4(2049.27,888.81) 2049.27,844.52 C33.2@1956.75,844.52 ; 2238.24,339.6 2238.24,377 2306.16,377 v1(2306.16,435.07) ; RA10.1@2257.73,251.99 2257.73,339.4 ; RA10.2@2307.73,251.99 2307.73,339.4 ; v1(2356.35,435.07) 2356.35,377 2423.28,377 2423.28,339.6 ; RA10.3@2357.73,251.99 2357.73,339.4 ; RA10.4@2407.73,251.99 2407.73,339.4 ; C34.1@2411.47,731.33 v1(2411.47,794.32) ; C26.2@2411.47,845.5 v1(2411.47,794.32) ; C21.2@2411.75,1081.51 2455.66,1081.5 2459.85,1077.32 v5(2473.48,1077.32) ; C12.2@2423.28,1517.75 2362.26,1517.75 v1(2362.26,1470.5) v1(2299.27,1470.5) 2299.27,1517.75 2238.24,1517.75 2238.24,1569.91 2124.07,1569.91 ; v1(2473.48,983.3) 2485.29,995.11 2561.08,995.11 2612.26,995.11 ; v5@2473.48,1077.79 2612.26,1077.79 ; v1(2473.48,1238.22) 2480.37,1231.33 2561.08,1231.33 2612.26,1231.33 2612.26,995.11 ; C35.2@2561.08,656.53 2629.98,656.53 ; 2612.26,794.32 v1(2411.47,794.32) ; v4(2704.76,1931.13) 2785.49,1931.13 JP2.1@2785.49,1740.58 ; C4.2@2741.2,1153.57 v1(2741.2,1200.82) ; C44.1@2767.77,314.99 2670.33,314.99 v1(2657.52,312.04) 2657.54,301.21 2539.43,301.21 2539.43,339.6 ; v3(2996.12,620.11) v3(2996.12,679.17) v3(2996.12,738.22) ; v3(3055.17,600.43) v3(3055.17,659.48) v3(3055.17,718.54) v3(3055.17,777.59) ; v3(3114.23,620.11) v3(3114.23,679.17) v3(3114.23,738.22) v3(3114.23,797.28) 3114.23,962.63 3614.23,962.63 3771.71,962.63 ; C13.2@3614.23,1454.76 3720.53,1454.76 v1(3720.53,1486.25) 3771.71,1486.25 3771.71,1372.08 3846.51,1372.08 ; R19.2@3736.28,645.7 3815.02,645.7 v1(3815.02,600.43) ; R14.1@3736.28,1135.86 3846.51,1135.86 ; C30.2@3771.71,879.95 3771.71,962.63 ; 3844.54,1372.08 3846.51,1372.08 ; v3(3907.54,1525.62) 3937.06,1525.62 v3(3937.06,1584.68) ; HDR3.20@3935.49,1840.58 3935.49,1840.86 3935.09,1931.13 v4(3980.37,1931.13) 4074.86,1931.13 4074.86,1427.2 4153.6,1427.2 4153.6,1494.17 4153.6,1557.12 ; D1.1@4102.42,945.99 4015.8,945.9 4015.8,163.42 4107.93,163.42 JP6.2@4107.93,104.36 ; 4299.27,1257.91 4165.41,1257.91 4165.41,1336.65 4232.65,1336.65 4299.27,1336.65 ; -1870.02,1466.57 v1(-1870.02,1116.17) -1767.66,1116.17 ; -1767.66,1116.17 -1330.65,1116.17 ; 1283.52,841.57 1283.52,999.05 ; 1283.52,841.57 v1(1283.52,691.96) 1283.52,660.46 1344.54,660.46 pad.0@1430.17,660.46 ; 1283.52,999.05 1283.52,1081.72 ; 1283.52,1081.72 1283.52,1231.33 1344.54,1231.33 1344.54,1279.56 ; 1344.54,1279.56 1344.54,1442.94 ; 1344.54,1442.94 1344.54,1461.65 v1(1308.13,1461.65) 1308.13,1494.13 1383.91,1569.91 1667.38,1569.91 ; v1(1430.17,514.8) pad.0@1430.17,660.46 ; v1(1430.17,514.8) v1(1484.31,513.81) 1602.42,513.81 v1(1602.42,451.8) 1602.42,339.6 1667.38,339.6 ; 1667.38,339.6 1780.57,339.6 ; 1667.38,1569.91 1781.55,1569.91 ; 1780.57,339.6 2423.28,339.6 ; 1781.55,1569.91 1895.72,1569.91 ; 1895.72,1569.91 1941,1569.91 ; 1941,1569.91 2009.9,1569.91 ; C33.2@1956.75,844.52 C23.2@1956.75,1053.18 ; 2009.9,1569.91 2124.07,1569.91 ; 2423.28,339.6 2539.43,339.6 ; 2539.43,339.6 2539.43,591.57 2629.98,591.57 2629.98,656.53 ; 2612.26,995.11 2612.26,705.74 2629.98,688.02 v1(2629.98,684.09) 2629.98,656.53 ; 3771.71,962.63 v1(3846.51,962.63) 3846.51,1135.86 ; 3846.51,1135.86 3846.51,1372.08
  other v2: -1767.66,1931.13 -1570.81,1931.13 -1373.96,1931.13 -1177.11,1931.13 -980.26,1931.13 -783.41,1931.13 -586.56,1931.13 -389.71,1931.13 -192.86,1931.13 3.99,1931.13 200.84,1931.13 397.69,1931.13 594.54,1931.13
HA2: HDR2.2 U1.191 | length 388.5
  Top Layer w7.87: HDR2.2@1635.49,1840.58 1691,1785.07 1691,1723.46 1720.21,1694.25 1759.55,1694.25 1783.52,1670.28 U1.191@1783.52,1536.45
HA3: HDR2.3 JP3.2 U1.189 | length 1060.3
  Top Layer w7.87: HDR2.3@1735.49,1740.58 1813.05,1663.02 v1(1813.05,1621.09) 1822.89,1609.28 U1.189@1822.89,1536.45
  Bottom Layer w7.87: JP3.2@1233.65,1321.29 1233.65,1501.35 1367.18,1634.87 1799.27,1634.87 v1(1813.05,1621.09)
HA4: HDR2.4 U1.188 | length 348.5
  Top Layer w7.87: HDR2.4@1735.49,1840.58 1785.49,1790.58 1785.49,1714.77 1842.57,1657.68 U1.188@1842.57,1536.45
HA5: HDR2.5 JP4.2 U1.187 | length 1452.9
  Top Layer w7.87: HDR2.5@1835.49,1740.58 1835.49,1687.04 1872.1,1650.43 v1(1872.1,1619.13) 1862.26,1609.28 U1.187@1862.26,1536.45
  Bottom Layer w7.87: JP4.2@1233.65,990.58 1233.65,1255.28 1275.65,1297.28 1275.65,1344.52 1249.4,1370.76 1249.4,1494.82 1373.7,1619.13 1757.92,1619.13 1785.48,1591.57 1844.54,1591.57 v1(1872.1,1619.13)
HA6: HDR2.6 U1.181 | length 388.5
  Top Layer w7.87: HDR2.6@1835.49,1840.58 1877.02,1799.05 1877.02,1713 1911.84,1678.18 1953.35,1678.18 1980.37,1651.16 U1.181@1980.37,1536.45
HA7: HDR2.7 U1.179 | length 239
  Top Layer w7.87: HDR2.7@1935.49,1740.58 2019.74,1656.33 U1.179@2019.74,1536.45
HA8: HDR2.8 U1.180 | length 390.6
  Top Layer w7.87: HDR2.8@1935.49,1840.58 1892.77,1797.87 1892.77,1719.52 1918.36,1693.93 1959.87,1693.93 2000.06,1653.74 U1.180@2000.06,1536.45
HA9: HDR2.9 U1.176 | length 222.1
  Top Layer w7.87: HDR2.9@2035.49,1740.58 2078.8,1697.28 U1.176@2078.8,1536.45
HA10: HDR2.10 U1.178 | length 348.2
  Top Layer w7.87: HDR2.10@2035.49,1840.58 1984.31,1789.4 1984.31,1718.54 2039.43,1663.42 U1.178@2039.43,1536.45
HA11: HDR2.11 U1.174 | length 211.3
  Top Layer w7.87: U1.174@2118.17,1536.45 2118.17,1678.18 2135.49,1695.5 HDR2.11@2135.49,1740.58
HA12: HDR2.12 U1.175 | length 330.9
  Top Layer w7.87: U1.175@2098.48,1536.45 2098.48,1703.77 2084.7,1717.55 2084.7,1789.8 HDR2.12@2135.49,1840.58
HA13: HDR2.13 U1.169 | length 212
  Top Layer w7.87: U1.169@2216.59,1536.45 2216.59,1628.85 2235.49,1647.75 HDR2.13@2235.49,1740.58
HA14: HDR2.14 U1.173 | length 344.6
  Top Layer w7.87: U1.173@2137.85,1536.45 2137.85,1657.51 2183.13,1702.79 2183.13,1788.22 HDR2.14@2235.49,1840.58
HA15: HDR2.15 U1.167 | length 237.1
  Top Layer w7.87: U1.167@2255.96,1536.45 2255.96,1623.68 2335.49,1703.21 HDR2.15@2335.49,1740.58
HA16: HDR2.16 U1.168 | length 345.2
  Top Layer w7.87: U1.168@2236.28,1536.45 2236.28,1626.27 2278.6,1668.59 2278.6,1783.69 HDR2.16@2335.49,1840.58
HA17: HDR2.17 U1.165 | length 272.6
  Top Layer w7.87: U1.165@2295.33,1536.45 2295.33,1618.14 2417.77,1740.58 HDR2.17@2435.49,1740.58
HA18: HDR2.18 U1.166 | length 370.3
  Top Layer w7.87: U1.166@2275.65,1536.45 2275.65,1621.09 2383.91,1729.36 2383.91,1789.01 HDR2.18@2435.49,1840.58
HA19: HDR2.19 U1.164 | length 351.4
  Top Layer w7.87: U1.164@2315.02,1536.45 2315.02,1615.56 2397.73,1698.27 2455.18,1698.27 2497.5,1740.58 HDR2.19@2535.49,1740.58
HARD_TCK: HDR1.3 U1.207 U5.6 | length 2962.9
  Top Layer w7.87: U1.207@1468.56,1536.45 v1(1468.56,1738.22) ; U5.6@2753.99,1348.46 2753.99,1300 2804.94,1249.06 v1(2804.94,1239.87)
  Bottom Layer w7.87: HDR1.3@1026.04,1848.46 1026.04,1878.38 1063.05,1915.39 2599.83,1915.39 2716.59,1798.63 2716.59,1672.28 ; v1(1468.56,1738.22) 1468.56,1915.39 ; 2716.59,1672.64 2725.45,1663.78 2725.45,1663.42 2894.74,1494.13 2894.74,1339.68 2804.94,1249.87 v1(2804.94,1239.87)
HARD_TDI: HDR1.1 U1.159 | length 1487
  Top Layer w7.87: U1.159@2413.44,1536.45 2413.44,1582.71 v1(2435.09,1604.36)
  Bottom Layer w7.87: HDR1.1@1126.04,1848.46 1212.65,1848.46 1410.49,1650.62 2388.83,1650.62 v1(2435.09,1604.36)
HARD_TDO: HDR1.2 U5.17 | length 2551
  Top Layer w7.87: U5.17@2805.17,1129.95 v1(2805.17,1192.94)
  Bottom Layer w7.87: HDR1.2@1126.04,1748.46 1074.84,1799.65 1074.84,1883.87 1090.61,1899.64 1189.03,1899.64 1422.3,1666.37 2700.22,1666.37 2748.97,1617.62 2878.99,1487.6 2878.99,1358.93 2775.26,1255.2 2775.26,1222.86 v1(2805.17,1192.94)
HARD_TMS: HDR1.4 U1.2 U5.5 | length 3274.4
  Top Layer w7.87: HDR1.4@1026.04,1748.46 1026.04,1683.1 1277.02,1432.12 U1.2@1364.23,1432.12 ; U5.5@2779.58,1348.46 2779.58,1307.12 2841.83,1244.87 v1(2854.94,1244.87)
  Bottom Layer w7.87: HDR1.4@1026.04,1748.46 982.34,1792.16 982.34,1870.11 1043.56,1931.33 2606.16,1931.33 2732.34,1805.15 2732.34,1679.17 2910.49,1501.02 2910.49,1325.43 2854.94,1269.87 v1(2854.94,1244.87)
HB2: HDR3.2 U1.163 | length 871.6
  Top Layer w7.87: U1.163@2334.7,1536.45 2334.7,1612.97 2404.25,1682.52 2840.76,1682.52 2972.57,1814.33 2998.82,1840.58 HDR3.2@3035.49,1840.58
HB3: HDR3.3 U1.160 | length 866.6
  Top Layer w7.87: U1.160@2393.76,1536.45 2393.76,1605.21 2423.82,1635.28 2860.33,1635.28 2923.23,1698.18 3072.22,1698.18 3114.62,1740.58 HDR3.3@3135.49,1740.58
HB4: HDR3.4 U1.162 | length 950.4
  Top Layer w7.87: U1.162@2354.39,1536.45 2354.39,1610.38 2410.78,1666.77 2847.28,1666.77 2978.77,1798.26 3093.17,1798.26 HDR3.4@3135.49,1840.58
HB5: HDR3.5 U1.138 | length 1290.1
  Top Layer w7.87: U1.138@2537.46,1097.47 2587.29,1097.47 2648.16,1036.6 2902.77,1036.6 2927.22,1061.06 2927.22,1530.91 3085.32,1689.01 3183.91,1689.01 HDR3.5@3235.49,1740.58
HB6: HDR3.6 U1.161 | length 1029.2
  Top Layer w7.87: U1.161@2374.07,1536.45 2374.07,1607.8 2417.3,1651.03 2853.81,1651.03 2985.29,1782.51 3177.42,1782.51 HDR3.6@3235.49,1840.58
HB7: HDR3.7 U1.135 | length 1423.7
  Top Layer w7.87: U1.135@2537.46,1038.42 2601.8,1038.42 2638.22,1002 2919.35,1002 2958.72,1041.37 2958.72,1517.86 3098.36,1657.51 3278.23,1657.51 3304.19,1683.47 3304.19,1684.09 3321.91,1684.09 3335.49,1697.67 HDR3.7@3335.49,1740.58
HB8: HDR3.8 U1.136 | length 1493.4
  Top Layer w7.87: U1.136@2537.46,1058.1 2604.39,1058.1 2644.74,1017.75 2909.5,1017.75 2942.97,1051.21 2942.97,1524.39 3091.84,1673.26 3271.71,1673.26 3288.44,1689.99 3288.44,1793.54 HDR3.8@3335.49,1840.58
HB9: HDR3.9 U1.133 | length 1552.2
  Top Layer w7.87: U1.133@2537.46,999.05 2595.53,999.05 2624.07,970.5 2939.03,970.5 2990.21,1021.68 2990.21,1380.94 2990.21,1504.82 3111.41,1626.02 3291.28,1626.02 3317.85,1652.59 3416.39,1652.59 3435.49,1671.69 HDR3.9@3435.49,1740.58
HB10: HDR3.10 U1.134 | length 1601
  Top Layer w7.87: U1.134@2537.46,1018.73 2598.11,1018.73 2630.59,986.25 2929.19,986.25 2974.46,1031.53 2974.46,1511.34 3104.89,1641.76 3284.75,1641.76 3311.33,1668.34 3356.35,1668.34 3386.87,1698.85 3386.87,1791.96 HDR3.10@3435.49,1840.58
HB11: HDR3.11 U1.129 | length 1671.6
  Top Layer w7.87: U1.129@2537.46,920.31 2599.46,920.31 2614.41,935.25 2952.99,935.25 3021.71,1003.97 3021.71,1403.57 3021.71,1491.77 3124.46,1594.52 3304.32,1594.52 3330.9,1621.09 3498.09,1621.09 3535.49,1658.5 HDR3.11@3535.49,1740.58
HB12: HDR3.12 U1.132 | length 1732.7
  Top Layer w7.87: U1.132@2537.46,979.36 2592.57,979.36 2617.18,954.76 2948.87,954.76 3005.96,1011.84 3005.96,1498.3 3117.93,1610.27 3297.8,1610.27 3324.38,1636.84 3455.76,1636.84 3485.29,1666.37 3485.29,1790.39 HDR3.12@3535.49,1840.58
HB13: HDR3.13 U1.126 | length 1837.4
  Top Layer w7.87: U1.126@2537.46,861.25 2609.31,861.25 2636.87,833.69 2898.68,833.69 3053.2,988.22 3053.2,1394.72 3053.2,1478.73 3137.5,1563.02 3317.37,1563.02 3342.96,1588.61 3594.44,1588.61 3635.49,1629.67 HDR3.13@3635.49,1740.58
HB14: HDR3.14 U1.127 | length 1902.4
  Top Layer w7.87: U1.127@2537.46,880.94 2613.24,880.94 2644.74,849.44 2890.8,849.44 3037.46,996.09 3037.46,1395.7 3037.46,1485.25 3130.98,1578.77 3310.85,1578.77 3336.44,1604.36 3560.09,1604.36 3583.72,1627.98 3583.72,1788.81 HDR3.14@3635.49,1840.58
HB15: HDR3.15 U1.123 | length 1908.1
  Top Layer w7.87: U1.123@2537.46,802.2 2914.43,802.2 3084.7,972.47 3084.7,1465.68 3150.55,1531.53 3330.42,1531.53 3356.01,1557.12 3607.48,1557.12 3735.49,1685.12 HDR3.15@3735.49,1740.58
HB16: HDR3.16 U1.125 | length 1997.5
  Top Layer w7.87: U1.125@2537.46,841.57 2605.37,841.57 2628.99,817.94 2906.55,817.94 3068.95,980.35 3068.95,1376.02 3068.95,1472.2 3144.03,1547.28 3323.89,1547.28 3349.48,1572.87 3600.96,1572.87 3685.09,1657 3685.09,1790.19 HDR3.16@3735.49,1840.58
HB17: HDR3.17 U1.121 | length 1993.2
  Top Layer w7.87: U1.121@2537.46,762.83 2921.68,762.83 3116.2,957.34 3116.2,1452.63 3163.59,1500.03 3343.46,1500.03 3368.07,1524.64 3619.54,1524.64 HDR3.17@3835.49,1740.58
HB18: HDR3.18 U1.122 | length 2072
  Top Layer w7.87: U1.122@2537.46,782.51 2919.1,782.51 3100.45,963.86 3100.45,1459.16 3157.07,1515.78 3336.94,1515.78 3362.53,1541.37 3614,1541.37 3787.46,1714.82 3787.46,1792.55 HDR3.18@3835.49,1840.58
HB19: HDR3.19 U1.120 | length 2101.3
  Top Layer w7.87: U1.120@2537.46,743.14 2924.27,743.14 3132.93,951.8 3132.93,1447.1 3170.12,1484.28 3349.98,1484.28 3374.59,1508.89 3627.02,1508.89 3794.97,1676.84 3871.74,1676.84 HDR3.19@3935.49,1740.58
I\N\I\T\: R5.2 U1.107 U5.8 | length 1282
  Top Layer w7.87: U1.107@2537.46,487.24 2622.1,487.24 v1(2631.94,477.39) ; v1(2664.43,1254.95) 2664.43,1270.7 2702.81,1309.09 U5.8@2702.81,1348.46 ; v1(2712.77,1457.9) R5.2@2763.83,1457.71
  Bottom Layer w7.87: v1(2631.94,477.39) 2675.25,520.7 2675.25,841.83 2664.43,852.66 2664.43,1409.55 v1(2712.77,1457.9)
JTAG_NEXUS_TCK: HDR1.7 U1.6 | length 779.1
  Top Layer w7.87: HDR1.7@826.04,1848.46 876.04,1798.46 876.04,1737.24 906.56,1706.72 932.15,1706.72 1285.49,1353.38 U1.6@1364.23,1353.38
JTAG_NEXUS_TDI: HDR1.5 U1.4 | length 679.3
  Top Layer w7.87: HDR1.5@926.04,1848.46 976.43,1798.06 976.43,1708.69 1292.38,1392.75 U1.4@1364.23,1392.75
JTAG_NEXUS_TDO: HDR1.6 U1.5 | length 601.3
  Top Layer w7.87: HDR1.6@926.04,1748.46 926.04,1735.46 1288.44,1373.06 U1.5@1364.23,1373.06
JTAG_NEXUS_TMS: HDR1.8 U1.7 | length 710
  Top Layer w7.87: HDR1.8@826.04,1748.46 883.52,1690.97 924.27,1690.97 1281.55,1333.69 U1.7@1364.23,1333.69
LCD_CONTRAST: LCD1.3 R1.W | length 825.3
  Top Layer w19.68: R1.W@-2346.4,1340.58 -2236.17,1340.58 -2192.86,1297.28 -1763.2,1297.28 -1630.65,1429.82 LCD1.3@-1630.65,1466.57
LCD_DB0: RA2.5 U1.20 | length 2710
  Top Layer w7.87: RA2.5@-1165.5,1188.03 -1165.5,1104.36 -1133.02,1071.88 -771.6,1071.88 -724.35,1024.64 138.24,1024.64 241.58,1127.98 1272.69,1127.98 1322.89,1077.79 U1.20@1364.23,1077.79
LCD_DB1: RA2.6 U1.18 | length 2640.6
  Top Layer w7.87: RA2.6@-1115.5,1188.03 -1115.5,1109.68 -1093.45,1087.63 -763.72,1087.63 -716.48,1040.39 131.71,1040.39 235.06,1143.73 1279.22,1143.73 1305.79,1117.16 U1.18@1364.23,1117.16
LCD_DB2: RA2.7 U1.17 | length 2577.1
  Top Layer w7.87: RA2.7@-1065.5,1188.03 -1065.5,1118.73 -1050.14,1103.38 -755.85,1103.38 -708.61,1056.13 125.19,1056.13 228.54,1159.48 1285.74,1159.48 1308.38,1136.84 U1.17@1364.23,1136.84
LCD_DB3: RA2.8 U1.16 | length 2513.7
  Top Layer w7.87: RA2.8@-1015.5,1188.03 -1015.5,1127.79 -1006.83,1119.13 -747.98,1119.13 -700.73,1071.88 118.67,1071.88 222.01,1175.23 1292.26,1175.23 1310.96,1156.53 U1.16@1364.23,1156.53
